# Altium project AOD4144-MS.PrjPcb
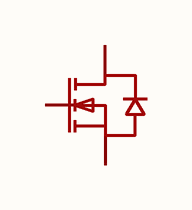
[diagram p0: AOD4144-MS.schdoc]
1 sheet, 1 parts. Net scope: global (net labels, ports and power ports of the same name join across sheets).

## Sheet AOD4144-MS.schdoc
size 127 x 101 mm

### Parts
Q?  aod4144-ms  [TO-252-3_L6.6-W6.1-P4.57-LS9.9-BR-CW]  (value not drawn)

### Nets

Not connected (* = marked no-connect by the designer): Q? 1(G) 2(D) 3(S)

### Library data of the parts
Q? = aod4144-ms: 类型:1个N沟道;漏源电压(Vdss):30V;连续漏极电流(Id):60A;导通电阻(RDS(on)):8.5mΩ@10V,15A;耗散功率(Pd):41W;阈值电压(Vgs(th)):1.5V;; Manufacturer: MSKSEMI(美森科); AddInBom: yes; ModelId: dee852f3c6b348a2b9d5be5dd3244081; ModelTransform: 258.97184,390.1567,0,90,0,0,-35.433,0,0; Type: 1个N沟道; Drain to Source Voltage: 30V; Current - Continuous Drain(Id): 60A; Pd - Power Dissipation(Pd): 41W; Gate Threshold Voltage (Vgs(th)@Id): 1.5V; Gate Charge(Qg): 17.6nC@4.5V; Input Capacitance(Ciss@Vds): 1.843nF@15V; Reverse Transfer Capacitance (Crss@Vds): 183pF@15V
